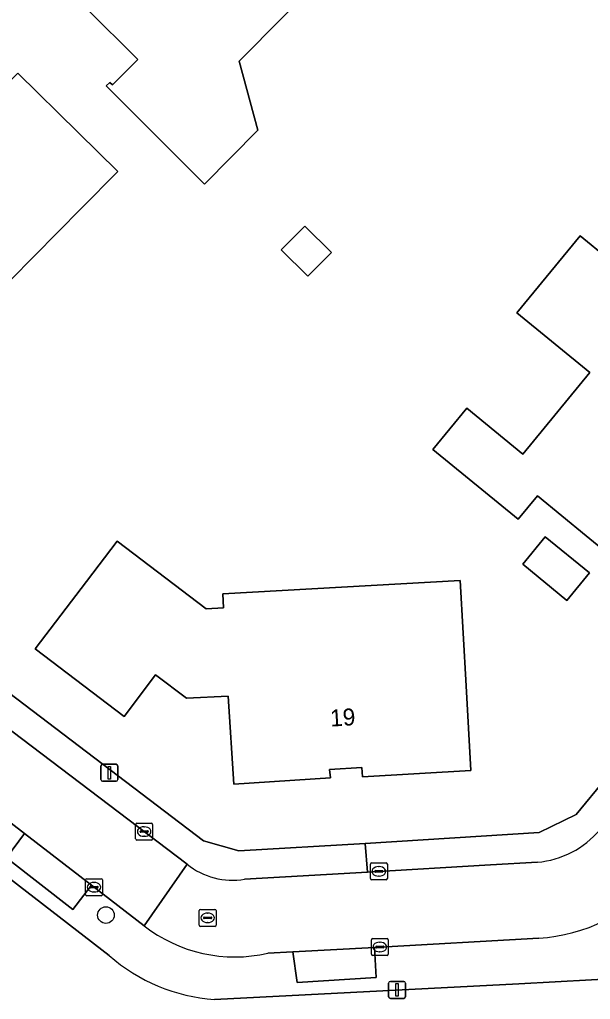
# Model space of a CAD drawing. Extents: x 159499 to 160349, y 382524 to 383273.
# Drawn here: x 159961.9 to 159995.6, y 382953.4 to 383011.1 of the extents above; entities that cross this region are included whole.
import ezdxf

# ---------------------------------------------------------------- set-up
doc = ezdxf.new("R2010")
doc.units = 0
for name, color, linetype in [('IMGEO_Boom', 7, 'Continuous'), ('IMGEO_Erf', 7, 'Continuous'), ('IMGEO_Kolk', 7, 'Continuous'), ('IMGEO_Lichtmast', 7, 'Continuous'), ('IMGEO_Pand', 7, 'Continuous'), ('IMGEO_Pand_nummerreeks', 7, 'Continuous'), ('IMGEO_Parkeervlak_open', 7, 'Continuous'), ('IMGEO_Rijbaan_lokaal_open', 7, 'Continuous'), ('IMGEO_Rioolput', 7, 'Continuous'), ('IMGEO_Voetpad_open', 7, 'Continuous')]:
    doc.layers.add(name, color=color, linetype=linetype)

msp = doc.modelspace()

# ---------------------------------------------------------------- linework, layer by layer
at = {"layer": 'IMGEO_Boom'}
msp.add_circle((159967.036, 382958.322), 0.489, dxfattribs=at)
at = {"layer": 'IMGEO_Erf'}
for points in [[(159974.891, 383008.662), (159975.996, 383004.592), (159972.853, 383001.418), (159967.057, 383007.206), (159967.262, 383007.411), (159967.418, 383007.256), (159968.909, 383008.749), (159965.866, 383011.787), (159969.736, 383015.708), (159971.215, 383017.206), (159970.564, 383017.814), (159973.308, 383020.573), (159976.861, 383017.055), (159980.062, 383013.885)], [(159965.407, 383004.45), (159967.731, 383002.163), (159965.595, 383000), (159960.002, 382994.338), (159957.827, 382996.487), (159954.269, 383000), (159953.963, 383000.302), (159957.182, 383003.594), (159957.552, 383003.245), (159959.681, 383005.434), (159959.519, 383005.605), (159961.844, 383007.958)], [(159980.324, 382997.388), (159978.941, 382995.991), (159977.371, 382997.545), (159978.755, 382998.942)], [(159988.303, 382988.208), (159991.605, 382985.499), (159995.547, 382990.302), (159991.259, 382993.822), (159994.989, 382998.368), (159998.247, 382995.694), (160000, 382994.256), (160000.702, 382993.68), (160004.567, 382990.508), (160004.377, 382990.277), (160003.327, 382991.149), (160000.703, 382987.888), (160001.735, 382987.044), (160004.866, 382984.483), (160004.681, 382984.243), (160003.922, 382984.861), (160000, 382980.058), (159998.643, 382978.396), (159999.406, 382977.748), (159999.206, 382977.516), (159995.341, 382980.688), (159992.465, 382983.047), (159991.323, 382981.656), (159986.305, 382985.773)], [(159987.908, 382978.054), (159988.265, 382971.829), (159988.551, 382966.837), (159982.16, 382966.482), (159982.117, 382967.02), (159980.216, 382966.903), (159980.265, 382966.415), (159974.571, 382966.048), (159974.248, 382971.235), (159971.787, 382971.11), (159969.948, 382972.492), (159968.113, 382970.035), (159962.862, 382974.012), (159965.887, 382977.994), (159967.689, 382980.367), (159972.945, 382976.375), (159973.964, 382976.433), (159973.916, 382977.252)], [(159995.535, 382978.492), (159994.204, 382976.87), (159991.603, 382979.004), (159992.933, 382980.626)]]:
    msp.add_lwpolyline(points, close=True, dxfattribs=at)
for points in [[(159937.661, 382989.432), (159947.551, 382981.884), (159972.788, 382962.692), (159974.862, 382962.113), (159982.324, 382962.546), (159992.571, 382963.192), (159994.756, 382964.255), (160000, 382970.621), (160005.936, 382977.853), (160024.041, 383000), (160036.566, 383015.316)], [(159967.231, 382955.939), (159938.787, 382977.935), (159934.243, 382981.423)], [(160000.149, 382954.763), (159999.933, 382954.745), (159991.369, 382954.262), (159973.432, 382953.353)]]:
    msp.add_lwpolyline(points, dxfattribs=at)
msp.add_arc((159974.163, 382963.833), 10.506, 228.71362, 266.01123, dxfattribs=at)
at = {"layer": 'IMGEO_Kolk'}
for p, q in [((159968.788, 382962.82), (159968.788, 382963.672)), ((159968.863, 382963.746), (159969.715, 382963.746)), ((159969.276, 382963.526), (159969.301, 382963.526)), ((159969.789, 382963.672), (159969.789, 382962.82)), ((159969.047, 382963.24), (159969.047, 382963.252)), ((159969.485, 382963.203), (159969.087, 382963.203)), ((159969.09, 382963.289), (159969.488, 382963.289)), ((159969.299, 382962.966), (159969.274, 382962.966)), ((159969.531, 382963.252), (159969.531, 382963.24)), ((159969.715, 382962.746), (159968.863, 382962.746)), ((159982.62, 382960.473), (159982.62, 382961.325)), ((159982.695, 382961.399), (159983.547, 382961.399)), ((159983.621, 382961.325), (159983.621, 382960.473)), ((159982.879, 382960.893), (159982.879, 382960.905)), ((159983.317, 382960.856), (159982.919, 382960.856)), ((159982.922, 382960.942), (159983.32, 382960.942)), ((159983.108, 382961.179), (159983.133, 382961.179)), ((159983.363, 382960.905), (159983.363, 382960.893)), ((159965.834, 382959.54), (159965.834, 382960.392)), ((159965.909, 382960.466), (159966.761, 382960.466)), ((159966.322, 382960.246), (159966.347, 382960.246)), ((159966.835, 382960.392), (159966.835, 382959.54)), ((159983.547, 382960.399), (159982.695, 382960.399)), ((159983.131, 382960.619), (159983.106, 382960.619)), ((159966.093, 382959.96), (159966.093, 382959.972)), ((159966.531, 382959.923), (159966.133, 382959.923)), ((159966.136, 382960.009), (159966.534, 382960.009)), ((159966.345, 382959.686), (159966.32, 382959.686)), ((159966.577, 382959.972), (159966.577, 382959.96)), ((159966.761, 382959.466), (159965.909, 382959.466)), ((159982.678, 382956.015), (159982.678, 382956.867)), ((159982.753, 382956.941), (159983.605, 382956.941)), ((159983.166, 382956.721), (159983.191, 382956.721)), ((159983.679, 382956.867), (159983.679, 382956.015)), ((159982.937, 382956.435), (159982.937, 382956.447)), ((159983.375, 382956.398), (159982.977, 382956.398)), ((159982.98, 382956.484), (159983.378, 382956.484)), ((159983.189, 382956.161), (159983.164, 382956.161)), ((159983.421, 382956.447), (159983.421, 382956.435)), ((159983.605, 382955.941), (159982.753, 382955.941))]:
    msp.add_line(p, q, dxfattribs=at)
for points in [[(159968.788, 382962.82), (159968.788, 382963.672)], [(159968.863, 382963.746), (159969.715, 382963.746)], [(159969.789, 382963.672), (159969.789, 382962.82)], [(159969.715, 382962.746), (159968.863, 382962.746)], [(159982.62, 382960.473), (159982.62, 382961.325)], [(159982.695, 382961.399), (159983.547, 382961.399)], [(159983.621, 382961.325), (159983.621, 382960.473)], [(159965.834, 382959.54), (159965.834, 382960.392)], [(159965.909, 382960.466), (159966.761, 382960.466)], [(159966.835, 382960.392), (159966.835, 382959.54)], [(159983.547, 382960.399), (159982.695, 382960.399)], [(159966.761, 382959.466), (159965.909, 382959.466)], [(159982.678, 382956.015), (159982.678, 382956.867)], [(159982.753, 382956.941), (159983.605, 382956.941)], [(159983.679, 382956.867), (159983.679, 382956.015)], [(159983.605, 382955.941), (159982.753, 382955.941)]]:
    msp.add_lwpolyline(points, dxfattribs=at)
for centre, radius, start, end in [((159968.865, 382963.67), 0.0765, 91.55205, 178.44795), ((159968.865, 382963.67), 0.0765, 91.55205, 178.44795), ((159969.713, 382963.67), 0.0765, 1.55205, 88.44795), ((159969.713, 382963.67), 0.0765, 1.55205, 88.44795), ((159969.087, 382963.249), 0.0403, 85.87752, 175.75265), ((159969.084, 382963.239), 0.0366, 178.93798, 274.71019), ((159969.488, 382963.246), 0.043, 264.86636, 352.45326), ((159969.492, 382963.251), 0.0386, 1.73085, 96.63898), ((159968.865, 382962.822), 0.0765, 181.55205, 268.44795), ((159968.865, 382962.822), 0.0765, 181.55205, 268.44795), ((159969.713, 382962.822), 0.0765, 271.55205, 358.44795), ((159969.713, 382962.822), 0.0765, 271.55205, 358.44795), ((159982.697, 382961.323), 0.0765, 91.55205, 178.44795), ((159982.697, 382961.323), 0.0765, 91.55205, 178.44795), ((159983.545, 382961.323), 0.0765, 1.55205, 88.44795), ((159983.545, 382961.323), 0.0765, 1.55205, 88.44795), ((159982.919, 382960.902), 0.0403, 85.87752, 175.75265), ((159982.916, 382960.892), 0.0366, 178.93798, 274.71019), ((159983.32, 382960.899), 0.043, 264.86636, 352.45326), ((159983.324, 382960.904), 0.0386, 1.73085, 96.63898), ((159965.911, 382960.39), 0.0765, 91.55205, 178.44795), ((159965.911, 382960.39), 0.0765, 91.55205, 178.44795), ((159966.759, 382960.39), 0.0765, 1.55205, 88.44795), ((159966.759, 382960.39), 0.0765, 1.55205, 88.44795), ((159982.697, 382960.475), 0.0765, 181.55205, 268.44795), ((159982.697, 382960.475), 0.0765, 181.55205, 268.44795), ((159983.545, 382960.475), 0.0765, 271.55205, 358.44795), ((159983.545, 382960.475), 0.0765, 271.55205, 358.44795), ((159965.911, 382959.542), 0.0765, 181.55205, 268.44795), ((159965.911, 382959.542), 0.0765, 181.55205, 268.44795), ((159966.133, 382959.969), 0.0403, 85.87752, 175.75265), ((159966.13, 382959.959), 0.0366, 178.93798, 274.71019), ((159966.534, 382959.966), 0.043, 264.86636, 352.45326), ((159966.538, 382959.971), 0.0386, 1.73085, 96.63898), ((159966.759, 382959.542), 0.0765, 271.55205, 358.44795), ((159966.759, 382959.542), 0.0765, 271.55205, 358.44795), ((159982.755, 382956.865), 0.0765, 91.55205, 178.44795), ((159982.755, 382956.865), 0.0765, 91.55205, 178.44795), ((159983.603, 382956.865), 0.0765, 1.55205, 88.44795), ((159983.603, 382956.865), 0.0765, 1.55205, 88.44795), ((159982.755, 382956.017), 0.0765, 181.55205, 268.44795), ((159982.755, 382956.017), 0.0765, 181.55205, 268.44795), ((159982.977, 382956.444), 0.0403, 85.87752, 175.75265), ((159982.974, 382956.434), 0.0366, 178.93798, 274.71019), ((159983.378, 382956.441), 0.043, 264.86636, 352.45326), ((159983.382, 382956.446), 0.0386, 1.73085, 96.63898), ((159983.603, 382956.017), 0.0765, 271.55205, 358.44795), ((159983.603, 382956.017), 0.0765, 271.55205, 358.44795)]:
    msp.add_arc(centre, radius, start, end, dxfattribs=at)
for centre, major_axis, ratio, start_param, end_param in [((159969.275, 382963.246), (-0.387, 0.002), 0.722429, 4.712389, 7.853982), ((159969.3, 382963.246), (-0.39, 0.002), 0.717154, 1.570796, 4.712389), ((159983.107, 382960.899), (-0.387, 0.002), 0.722429, 4.712389, 7.853982), ((159983.132, 382960.899), (-0.39, 0.002), 0.717154, 1.570796, 4.712389), ((159966.321, 382959.966), (-0.387, 0.002), 0.722429, 4.712389, 7.853982), ((159966.346, 382959.966), (-0.39, 0.002), 0.717154, 1.570796, 4.712389), ((159983.165, 382956.441), (-0.387, 0.002), 0.722429, 4.712389, 7.853982), ((159983.19, 382956.441), (-0.39, 0.002), 0.717154, 1.570796, 4.712389)]:
    msp.add_ellipse(centre, major_axis=major_axis, ratio=ratio, start_param=start_param, end_param=end_param, dxfattribs=at)
at = {"layer": 'IMGEO_Lichtmast'}
for p, q in [((159966.74, 382966.312), (159966.74, 382967.112)), ((159966.74, 382967.112), (159966.74, 382966.312)), ((159966.84, 382967.212), (159967.63, 382967.212)), ((159967.63, 382967.212), (159966.84, 382967.212)), ((159967.73, 382967.112), (159967.73, 382966.312)), ((159967.73, 382966.312), (159967.73, 382967.112)), ((159967.63, 382966.212), (159966.84, 382966.212)), ((159966.84, 382966.212), (159967.63, 382966.212)), ((159983.699, 382953.514), (159983.699, 382954.314)), ((159983.699, 382954.314), (159983.699, 382953.514)), ((159983.799, 382954.414), (159984.589, 382954.414)), ((159984.589, 382954.414), (159983.799, 382954.414)), ((159984.689, 382954.314), (159984.689, 382953.514)), ((159984.689, 382953.514), (159984.689, 382954.314)), ((159984.589, 382953.414), (159983.799, 382953.414)), ((159983.799, 382953.414), (159984.589, 382953.414))]:
    msp.add_line(p, q, dxfattribs=at)
for points in [[(159967.16, 382967.087), (159967.31, 382967.087), (159967.31, 382966.337), (159967.16, 382966.337), (159967.16, 382967.087)], [(159984.119, 382954.289), (159984.269, 382954.289), (159984.269, 382953.539), (159984.119, 382953.539), (159984.119, 382954.289)]]:
    msp.add_lwpolyline(points, dxfattribs=at)
for centre, start, end in [((159966.84, 382967.112), 90, 180), ((159966.84, 382967.112), 90, 180), ((159967.63, 382967.112), 0, 90), ((159967.63, 382967.112), 360, 90), ((159966.84, 382966.312), 180, 270), ((159966.84, 382966.312), 180, 270), ((159967.63, 382966.312), 270, 0), ((159967.63, 382966.312), 270, 0), ((159983.799, 382954.314), 90, 180), ((159983.799, 382954.314), 90, 180), ((159984.589, 382954.314), 0, 90), ((159984.589, 382954.314), 360, 90), ((159983.799, 382953.514), 180, 270), ((159983.799, 382953.514), 180, 270), ((159984.589, 382953.514), 270, 0), ((159984.589, 382953.514), 270, 0)]:
    msp.add_arc(centre, 0.1, start, end, dxfattribs=at)
at = {"layer": 'IMGEO_Pand'}
for points in [[(159970.564, 383017.814), (159971.215, 383017.206), (159969.736, 383015.708), (159965.866, 383011.787), (159968.909, 383008.749), (159967.418, 383007.256), (159967.262, 383007.411), (159967.057, 383007.206), (159972.853, 383001.418), (159975.996, 383004.592), (159974.891, 383008.662), (159980.062, 383013.885), (159976.861, 383017.055), (159973.308, 383020.573)], [(159965.407, 383004.45), (159961.844, 383007.958), (159959.519, 383005.605), (159959.681, 383005.434), (159957.552, 383003.245), (159957.182, 383003.594), (159953.963, 383000.302), (159954.269, 383000), (159957.827, 382996.487), (159960.002, 382994.338), (159965.595, 383000), (159967.731, 383002.163)], [(159980.324, 382997.388), (159978.755, 382998.942), (159977.371, 382997.545), (159978.941, 382995.991)], [(159995.341, 382980.688), (159999.206, 382977.516), (159999.406, 382977.748), (159998.643, 382978.396), (160000, 382980.058), (160003.922, 382984.861), (160004.681, 382984.243), (160004.866, 382984.483), (160001.735, 382987.044), (160000.703, 382987.888), (160003.327, 382991.149), (160004.377, 382990.277), (160004.567, 382990.508), (160000.702, 382993.68), (160000, 382994.256), (159998.247, 382995.694), (159994.989, 382998.368), (159991.259, 382993.822), (159995.547, 382990.302), (159991.605, 382985.499), (159988.303, 382988.208), (159986.305, 382985.773), (159991.323, 382981.656), (159992.465, 382983.047)], [(159988.265, 382971.829), (159987.908, 382978.054), (159973.916, 382977.252), (159973.964, 382976.433), (159972.945, 382976.375), (159967.689, 382980.367), (159965.887, 382977.994), (159962.862, 382974.012), (159968.113, 382970.035), (159969.948, 382972.492), (159971.787, 382971.11), (159974.248, 382971.235), (159974.571, 382966.048), (159980.265, 382966.415), (159980.216, 382966.903), (159982.117, 382967.02), (159982.16, 382966.482), (159988.551, 382966.837)], [(159995.535, 382978.492), (159992.933, 382980.626), (159991.603, 382979.004), (159994.204, 382976.87)]]:
    msp.add_lwpolyline(points, close=True, dxfattribs=at)
at = {"layer": 'IMGEO_Parkeervlak_open'}
for points in [[(159962.244, 382963.13), (159961.175, 382961.695), (159965.084, 382958.658), (159966.186, 382960.084)], [(159978.059, 382956.156), (159978.306, 382954.358), (159982.969, 382954.641), (159982.87, 382956.422)]]:
    msp.add_lwpolyline(points, close=True, dxfattribs=at)
at = {"layer": 'IMGEO_Rijbaan_lokaal_open'}
for points in [[(159935.974, 382983.418), (159943.932, 382977.28), (159948.338, 382973.876), (159952.293, 382970.819), (159962.244, 382963.13), (159966.186, 382960.084), (159969.281, 382957.692), (159971.819, 382961.325), (159946.588, 382980.466)], [(159934.243, 382981.423), (159938.787, 382977.935), (159967.231, 382955.939)], [(159969.281, 382957.692), (159966.186, 382960.084), (159965.084, 382958.658), (159961.175, 382961.695), (159962.244, 382963.13), (159952.293, 382970.819), (159951.192, 382969.404), (159947.245, 382972.454)], [(159971.819, 382961.325), (159969.281, 382957.692)], [(159992.466, 382961.44), (159989.696, 382961.282), (159982.453, 382960.859), (159975.211, 382960.437)], [(159973.432, 382953.353), (159991.369, 382954.262), (159999.933, 382954.745), (160000.149, 382954.763), (160001.602, 382955.996), (160005.908, 382960.021), (160006.829, 382960.689)], [(159992.548, 382956.964), (159982.87, 382956.422), (159982.969, 382954.641), (159978.306, 382954.358), (159978.059, 382956.156), (159976.584, 382956.075)], [(159976.584, 382956.075), (159978.059, 382956.156), (159982.87, 382956.422), (159992.548, 382956.964)]]:
    msp.add_lwpolyline(points, dxfattribs=at)
for centre, radius, start, end in [((159991.996, 382966.848), 5.428, 274.96674, 319.79745), ((159974.502, 382964.651), 4.273, 231.10783, 279.55143), ((159991.946, 382966.989), 10.043, 273.43578, 319.56407), ((159991.946, 382966.989), 10.043, 273.43578, 319.56407), ((159974.645, 382964.619), 8.761, 232.24499, 282.78546), ((159974.645, 382964.619), 8.761, 232.24499, 282.78546), ((159974.163, 382963.833), 10.506, 228.71362, 266.01123)]:
    msp.add_arc(centre, radius, start, end, dxfattribs=at)
at = {"layer": 'IMGEO_Rioolput'}
for p, q in [((159972.531, 382957.733), (159972.531, 382958.585)), ((159972.606, 382958.659), (159973.458, 382958.659)), ((159973.019, 382958.439), (159973.044, 382958.439)), ((159973.532, 382958.585), (159973.532, 382957.733)), ((159972.79, 382958.153), (159972.79, 382958.165)), ((159973.228, 382958.116), (159972.83, 382958.116)), ((159972.833, 382958.202), (159973.231, 382958.202)), ((159973.042, 382957.879), (159973.017, 382957.879)), ((159973.274, 382958.165), (159973.274, 382958.153)), ((159973.458, 382957.659), (159972.606, 382957.659))]:
    msp.add_line(p, q, dxfattribs=at)
for points in [[(159972.531, 382957.733), (159972.531, 382958.585)], [(159972.606, 382958.659), (159973.458, 382958.659)], [(159973.532, 382958.585), (159973.532, 382957.733)], [(159973.458, 382957.659), (159972.606, 382957.659)]]:
    msp.add_lwpolyline(points, dxfattribs=at)
for centre, radius, start, end in [((159972.608, 382958.583), 0.0765, 91.55205, 178.44795), ((159972.608, 382958.583), 0.0765, 91.55205, 178.44795), ((159973.456, 382958.583), 0.0765, 1.55205, 88.44795), ((159973.456, 382958.583), 0.0765, 1.55205, 88.44795), ((159972.83, 382958.162), 0.0403, 85.87752, 175.75265), ((159972.827, 382958.152), 0.0366, 178.93798, 274.71019), ((159973.231, 382958.159), 0.043, 264.86636, 352.45326), ((159973.235, 382958.164), 0.0386, 1.73085, 96.63898), ((159972.608, 382957.735), 0.0765, 181.55205, 268.44795), ((159972.608, 382957.735), 0.0765, 181.55205, 268.44795), ((159973.456, 382957.735), 0.0765, 271.55205, 358.44795), ((159973.456, 382957.735), 0.0765, 271.55205, 358.44795)]:
    msp.add_arc(centre, radius, start, end, dxfattribs=at)
for centre, major_axis, ratio, start_param, end_param in [((159973.018, 382958.159), (-0.387, 0.002), 0.722429, 4.712389, 7.853982), ((159973.043, 382958.159), (-0.39, 0.002), 0.717154, 1.570796, 4.712389)]:
    msp.add_ellipse(centre, major_axis=major_axis, ratio=ratio, start_param=start_param, end_param=end_param, dxfattribs=at)
at = {"layer": 'IMGEO_Voetpad_open'}
for points in [[(160026.095, 383000), (160037.807, 383014.31), (160036.846, 383015.097), (160036.566, 383015.316), (160024.041, 383000), (160005.936, 382977.853), (160000, 382970.621), (159994.756, 382964.255), (159992.571, 382963.192), (159982.324, 382962.546), (159982.453, 382960.859), (159989.696, 382961.282), (159992.466, 382961.44)], [(159936.514, 382988.127), (159946.588, 382980.466), (159971.819, 382961.325)], [(159975.211, 382960.437), (159982.453, 382960.859), (159982.324, 382962.546), (159974.862, 382962.113), (159972.788, 382962.692), (159947.551, 382981.884)]]:
    msp.add_lwpolyline(points, dxfattribs=at)
for centre, radius, start, end in [((159991.996, 382966.848), 5.428, 274.96674, 319.79745), ((159974.502, 382964.651), 4.273, 231.10783, 279.55143)]:
    msp.add_arc(centre, radius, start, end, dxfattribs=at)

# ---------------------------------------------------------------- texts
at = {"layer": 'IMGEO_Pand_nummerreeks'}
msp.add_text('19', height=1, rotation=3.52192, dxfattribs=at).set_placement((159980.277, 382969.432))

doc.saveas('drawing.dxf')
